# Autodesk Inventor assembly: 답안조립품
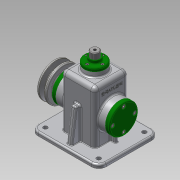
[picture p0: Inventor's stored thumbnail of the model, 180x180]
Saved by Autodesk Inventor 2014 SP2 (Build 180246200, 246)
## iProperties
Created: 2016-08
Part Number: 답안조립품
Document SubType Name: Assembly
Designer: user
Author: user
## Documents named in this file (19)
- C:\Users\user\Desktop\460820V1011\답안조립품.iam
- C:\Users\user\Desktop\460820V1011\본체.ipt
- C:\Users\user\Desktop\460820V1011\뒤커버.ipt
- C:\Users\user\Desktop\460820V1011\앞커버.ipt
- C:\Users\user\Desktop\460820V1011\베어링 15 x 35 x 11.ipt
- C:\Users\user\Desktop\460820V1011\편심축.ipt
- C:\Users\user\Desktop\460820V1011\링크.ipt
- C:\Users\user\Desktop\460820V1011\슬라이드바.ipt
- C:\Users\user\Desktop\460820V1011\고정핀.ipt
- C:\Users\user\Desktop\460820V1011\멈춤링 6 x 5.ipt
- C:\Users\user\Desktop\460820V1011\멈춤링 15 x 1.ipt
- C:\Users\user\Desktop\460820V1011\볼트 M4 x 10.ipt
- C:\Users\user\Desktop\460820V1011\오일실 15 25 7.ipt
- C:\Users\user\Desktop\460820V1011\키 5 x 5 x 14.ipt
- C:\Users\user\Desktop\460820V1011\V-벨트풀리.ipt
- C:\Users\user\Desktop\460820V1011\와셔.ipt
- C:\Users\user\Desktop\460820V1011\볼트 M6 x 12.ipt
- C:\Users\user\Desktop\460820V1011\상부부시.ipt
- C:\Users\user\Desktop\460820V1011\볼트 M3 x 8.ipt
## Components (15 placed, 5 different names)
1. 고정핀:1
2. V-벨트풀리:1 — 각도:1
3. ISO 4018 M6 x 12:1 — 강체:3
4. ISO 4762 M4 x 10:1 — 강체:1
5. ISO 4762 M4 x 10:3
6. ISO 4762 M4 x 10:4
7. ISO 4762 M4 x 10:5
8. ISO 4762 M4 x 10:2 — 강체:2
9. ISO 4762 M4 x 10:6
10. ISO 4762 M4 x 10:7
11. ISO 4762 M4 x 10:8
12. ISO 4762 M3 x 8:1 — 강체:4
13. ISO 4762 M3 x 8:2
14. ISO 4762 M3 x 8:3
15. ISO 4762 M3 x 8:4
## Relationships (5: WeldJoint 4, Angle 1)
- 강체:1 [WeldJoint]: ISO 4762 M4 x 10:1
- 강체:2 [WeldJoint]: ISO 4762 M4 x 10:2
- 각도:1 [Angle]: V-벨트풀리:1
- 강체:3 [WeldJoint]: ISO 4018 M6 x 12:1
- 강체:4 [WeldJoint]: ISO 4762 M3 x 8:1
